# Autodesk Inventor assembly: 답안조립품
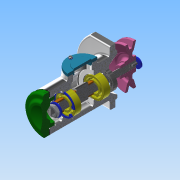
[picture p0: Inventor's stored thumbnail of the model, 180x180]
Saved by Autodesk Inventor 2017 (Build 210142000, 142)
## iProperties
Part Number: 답안조립품
Material: 일반
Document SubType Name: Assembly
Designer: MRC
Author: MRC
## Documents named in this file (22)
- C:\Users\MRC\Desktop\720506V1012\답안조립품.iam
- C:\Users\MRC\Desktop\720506V1012\본체.ipt
- C:\Users\MRC\Desktop\720506V1012\V-벨트풀리.ipt
- C:\Users\MRC\Desktop\720506V1012\개스킷.ipt
- C:\Users\MRC\Desktop\720506V1012\너트 M10.ipt
- C:\Users\MRC\Desktop\720506V1012\멈춤나사 M3.ipt
- C:\Users\MRC\Desktop\720506V1012\멈춤링 15 x 1.ipt
- C:\Users\MRC\Desktop\720506V1012\멈춤링 35 x 1.6.ipt
- C:\Users\MRC\Desktop\720506V1012\베어링 6202.ipt
- C:\Users\MRC\Desktop\720506V1012\볼트 M4 x 10.ipt
- C:\Users\MRC\Desktop\720506V1012\부시1.ipt
- C:\Users\MRC\Desktop\720506V1012\부시2.ipt
- C:\Users\MRC\Desktop\720506V1012\사이드 커버.ipt
- 사이드 커버.ipt
- C:\Users\MRC\Desktop\720506V1012\십자볼트 M3 x 10.ipt
- C:\Users\MRC\Desktop\720506V1012\오일 실 15 x 30 x 7.ipt
- C:\Users\MRC\Desktop\720506V1012\와셔 3 x 6.ipt
- C:\Users\MRC\Desktop\720506V1012\와셔 4 x 16.ipt
- C:\Users\MRC\Desktop\720506V1012\와셔 10 x 21.ipt
- C:\Users\MRC\Desktop\720506V1012\축.ipt
- C:\Users\MRC\Desktop\720506V1012\키 4 x 4.ipt
- C:\Users\MRC\Desktop\720506V1012\탑 커버.ipt
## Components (3 placed, 3 different names)
1. V-벨트풀리:1 — 플러쉬:1
2. 개스킷:1
3. ISO 4017 M4 x 10:1
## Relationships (1: Flush 1)
- 플러쉬:1 [Flush]: V-벨트풀리:1
